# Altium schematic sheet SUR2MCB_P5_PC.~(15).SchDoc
size 420 x 297 mm; Scale: 1:1; Обозначение документа: АБВГ.123456.001 Э3
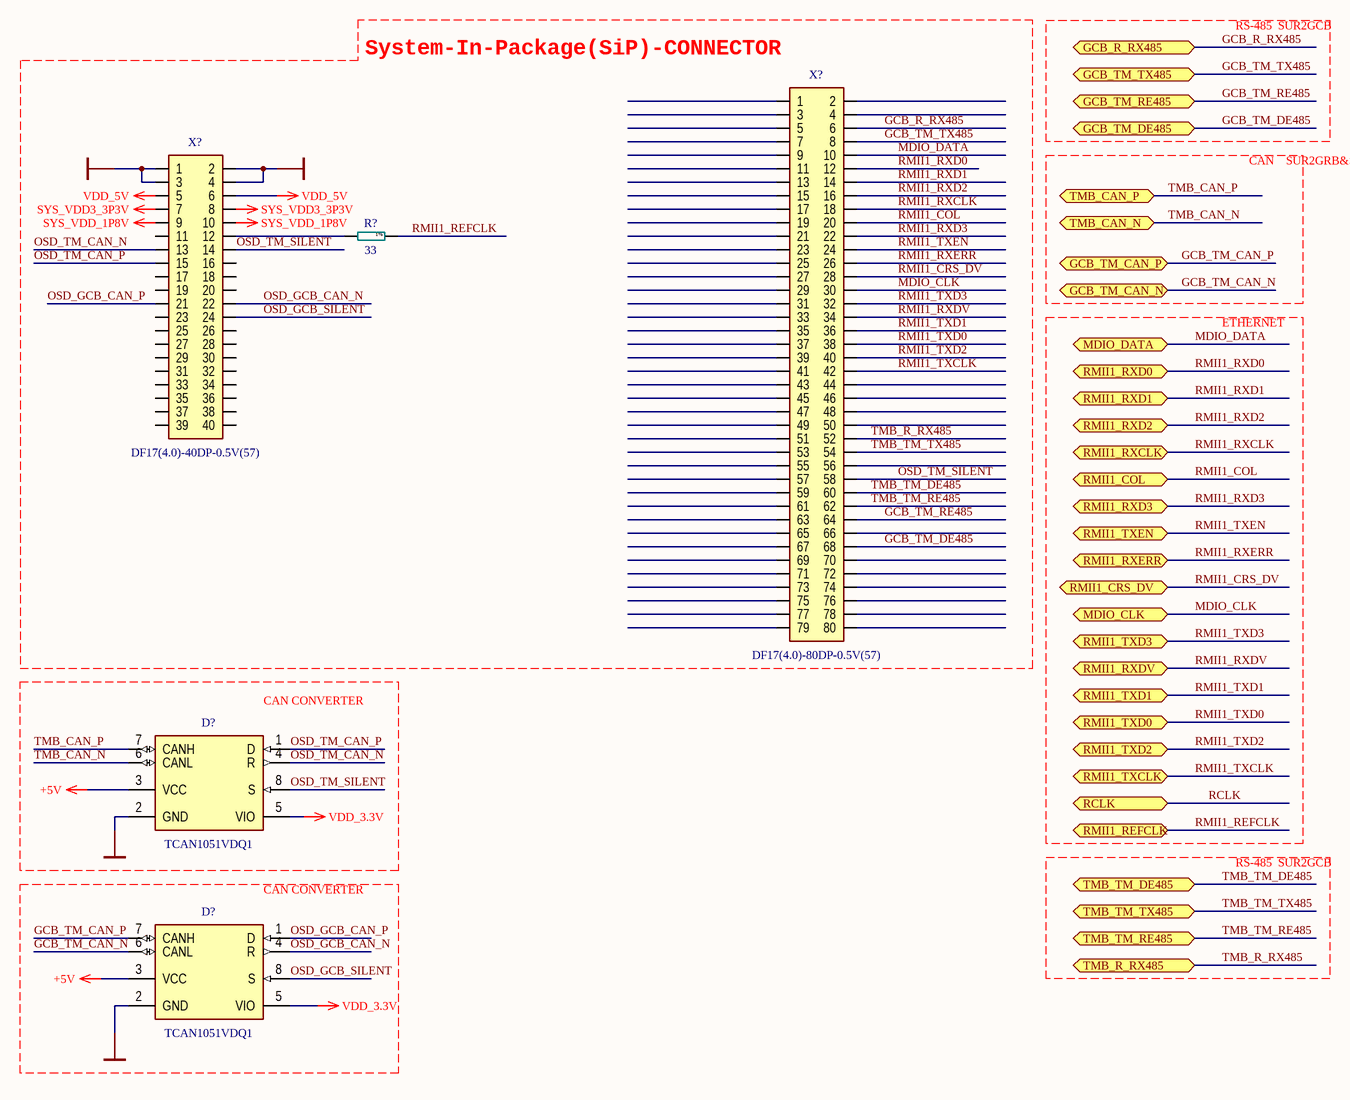
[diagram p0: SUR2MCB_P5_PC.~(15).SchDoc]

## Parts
(Parts that share a designator on the sheet are numbered #1, #2 ... from top to bottom, then left to right.)
D?#1  value TCAN1051VDQ1  [SOP-8-3.9X5-1.27]
D?#2  value TCAN1051VDQ1  [SOP-8-3.9X5-1.27]
R?  value 33  [R0402]
X?#1  value DF17(4.0)-80DP-0.5V(57)  [DF17(4.0)-80DP-0.5V(57)]
X?#2  value DF17(4.0)-40DP-0.5V(57)  [DF17(4.0)-40DP-0.5V(57)]

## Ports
GCB_R_RX485 (bidir), GCB_TM_CAN_N (bidir), GCB_TM_CAN_P (bidir), GCB_TM_DE485 (bidir), GCB_TM_RE485 (bidir), GCB_TM_TX485 (bidir), MDIO_CLK (bidir), MDIO_DATA (bidir), RCLK (bidir), RMII1_COL (bidir), RMII1_CRS_DV (bidir), RMII1_REFCLK (bidir), RMII1_RXCLK (bidir), RMII1_RXD0 (bidir), RMII1_RXD1 (bidir), RMII1_RXD2 (bidir), RMII1_RXD3 (bidir), RMII1_RXDV (bidir), RMII1_RXERR (bidir), RMII1_TXCLK (bidir), RMII1_TXD0 (bidir), RMII1_TXD1 (bidir), RMII1_TXD2 (bidir), RMII1_TXD3 (bidir), RMII1_TXEN (bidir), TMB_CAN_N (bidir), TMB_CAN_P (bidir), TMB_R_RX485 (bidir), TMB_TM_DE485 (bidir), TMB_TM_RE485 (bidir), TMB_TM_TX485 (bidir)

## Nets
+5V: D?#1.3(VCC) D?#2.3(VCC)
GND: D?#1.2(GND) D?#2.2(GND) X?#2.1 X?#2.2 X?#2.3 X?#2.4
SYS_VDD3_3P3V: X?#2.7 X?#2.8
SYS_VDD_1P8V: X?#2.9 X?#2.10
VDD_3.3V: D?#1.5(VIO) D?#2.5(VIO)
VDD_5V: X?#2.5 X?#2.6
GCB_R_RX485: X?#1.6 ; port GCB_R_RX485
GCB_TM_CAN_N: D?#2.6(CANL) ; port GCB_TM_CAN_N
GCB_TM_CAN_P: D?#2.7(CANH) ; port GCB_TM_CAN_P
GCB_TM_DE485: X?#1.68 ; port GCB_TM_DE485
GCB_TM_RE485: X?#1.64 ; port GCB_TM_RE485
GCB_TM_TX485: X?#1.8 ; port GCB_TM_TX485
MDIO_CLK: X?#1.30 ; port MDIO_CLK
MDIO_DATA: X?#1.10 ; port MDIO_DATA
OSD_GCB_CAN_N: D?#2.4(R) X?#2.22
OSD_GCB_CAN_P: D?#2.1(D) X?#2.21
OSD_GCB_SILENT: D?#2.8(S) X?#2.24
OSD_TM_CAN_N: D?#1.4(R) X?#2.13
OSD_TM_CAN_P: D?#1.1(D) X?#2.15
OSD_TM_SILENT: D?#1.8(S) X?#1.58 X?#2.14
RMII1_COL: X?#1.20 ; port RMII1_COL
RMII1_CRS_DV: X?#1.28 ; port RMII1_CRS_DV
RMII1_REFCLK: R?.2 ; port RMII1_REFCLK
RMII1_RXCLK: X?#1.18 ; port RMII1_RXCLK
RMII1_RXD0: X?#1.12 ; port RMII1_RXD0
RMII1_RXD1: X?#1.14 ; port RMII1_RXD1
RMII1_RXD2: X?#1.16 ; port RMII1_RXD2
RMII1_RXD3: X?#1.22 ; port RMII1_RXD3
RMII1_RXDV: X?#1.34 ; port RMII1_RXDV
RMII1_RXERR: X?#1.26 ; port RMII1_RXERR
RMII1_TXCLK: X?#1.42 ; port RMII1_TXCLK
RMII1_TXD0: X?#1.38 ; port RMII1_TXD0
RMII1_TXD1: X?#1.36 ; port RMII1_TXD1
RMII1_TXD2: X?#1.40 ; port RMII1_TXD2
RMII1_TXD3: X?#1.32 ; port RMII1_TXD3
RMII1_TXEN: X?#1.24 ; port RMII1_TXEN
TMB_CAN_N: D?#1.6(CANL) ; port TMB_CAN_N
TMB_CAN_P: D?#1.7(CANH) ; port TMB_CAN_P
TMB_R_RX485: X?#1.52 ; port TMB_R_RX485
TMB_TM_DE485: X?#1.60 ; port TMB_TM_DE485
TMB_TM_RE485: X?#1.62 ; port TMB_TM_RE485
TMB_TM_TX485: X?#1.54 ; port TMB_TM_TX485
NetR?_1: R?.1 X?#2.12

Not connected (* = marked no-connect by the designer): X?#1 1 2 3 4 5 7 9 11 13 15 17 19 21 23 25 27 29 31 33 35 37 39 41 43 44 45 46 47 48 49 50 51 53 55 56 57 59 61 63 65 66 67 69 70 71 72 73 74 75 76 77 78 79 80; X?#2 11 16 17 18 19 20 23 25 26 27 28 29 30 31 32 33 34 35 36 37 38 39 40

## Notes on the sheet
- System-In-Package(SiP)-CONNECTOR
- RS-485  SUR2GCB
- CAN    SUR2GRB&SUR2GCB
- ETHERNET
- (near D?#1) CAN CONVERTER
- (near D?#2) CAN CONVERTER

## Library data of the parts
D?#1 D?#2 = TCAN1051VDQ1: CAN Transceiver 8-SOIC 5V; ValueManufacturer: Texas Instruments; PowerVoltage: 4.5V~5.5V; ValueDescription: TCAN1051VDQ1  CAN приемопередатчик 4.5V~5.5V  8-SOIC (3.90mm)
R? = R-0402-1%: SMD 0402 0.1Вт ±1% 50В; ValueManufacturer: Panasonic; ValueManufacturerPartNumber: ERJ-2RK; PowerVoltage: 0.1Вт 50В; ValueDescription: 0402 (1005)  0.1Вт 50В  33Ом ±1%; ValueType: Chip Resistor
X?#1 = DF17(4.0)-80DP-0.5V(57): CONN HEADER 80POS .5MM SMD W/FIT; ValueManufacturer: Hirose Electric Co Ltd; PowerVoltage: 50V; TechSpec: Шаг 0.5; ValueDescription: DF17(4.0)-80DP-0.5V(57) Двухрядная вилка Hirose Electric Co Ltd  25.2x4.7mm  Шаг 0.5; ValueType: Connector
X?#2 = DF17(4.0)-40DP-0.5V(57): CONN HEADER 40POS .5MM SMD W/FIT; ValueManufacturer: Hirose Electric Co Ltd; PowerVoltage: 50V; TechSpec: Шаг 0.5; ValueDescription: DF17(4.0)-40DP-0.5V(57) Двухрядная вилка Hirose Electric Co Ltd  15.2x4.7mm  Шаг 0.5; ValueType: Connector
